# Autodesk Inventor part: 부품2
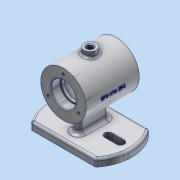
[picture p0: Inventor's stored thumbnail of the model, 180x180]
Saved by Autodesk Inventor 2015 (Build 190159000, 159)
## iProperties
Created: 2017-12
Part Number: 부품2
Material: 알루미늄 6061
Document SubType Name: Modeling
Designer: SCD-A03
Density: 2.7 g/cm^3
Appearance: 알루미늄 - 평지
Mass: 465.937 g
Surface Area: 486.734 cm^2
Volume: 172.569 cm^3
Author: SCD-A03
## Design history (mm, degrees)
node "스케치1"
sketch "스케치2"
  geometry: L1 (-42.426, 35)-(42.426, 35); L2 (42.426, -35)-(-42.426, -35); A1 r 55 centre (0, 0) between (-42.426, 35) and (-42.426, -35); A2 r 55 centre (0, 0) between (42.426, -35) and (42.426, 35); 2 further points
  constraints: 4 end point, 4 point on circle, 2 centre point, 1 coincident, 1 horizontal, 1 midpoint, 1 parallel, 1 vertical alignment
  dimensions: "d2" = 84.85281 distance of L2.start L2.end; "d3" = 55 radius of A1; "d4" = 70 distance between parallel lines of L2 L1; "d5" = 55 radius of A2
extrude "돌출1" new body sketch "스케치2" distance "d6" = 10; taper "d7" = 0 deg
sketch "스케치3"
  geometry: L1 (-40, 0)-(-24, 0); L2 (-40, -5)-(-24, -5); L3 (-24, 5)-(-40, 5); A1 r 55 centre (0, 0) between (-42.426, 35) and (-42.426, -35) reference; A2 r 5 centre (-40, 0) between (-40, 5) and (-40, -5); A3 r 5 centre (-24, 0) between (-24, -5) and (-24, 5); 1 further point
  constraints: 8 end point, 4 point on circle, 4 tangent, 2 centre point, 1 horizontal, 1 horizontal alignment, 1 midpoint, 1 parallel
  dimensions: "d8" = 16 distance of L3.start L3.end; "d9" = 24 horizontal distance of A1.centre L3.start; "d11" = 5 radius of A2
extrude "돌출2" cut sketch "스케치3" distance "d12" = 10; taper "d13" = 0 deg
sketch "스케치8"
  geometry: L1 (0, -15)-(0, 15); L2 (-5, -15)-(-5, 15); L3 (5, 15)-(5, -15); A1 r 55 centre (0, 0) between (-42.426, 35) and (-42.426, -35) reference; A2 r 5 centre (0, -15) between (-5, -15) and (5, -15); A3 r 5 centre (0, 15) between (5, 15) and (-5, 15); 1 further point
  constraints: 8 end point, 4 point on circle, 4 tangent, 2 centre point, 1 coincident, 1 midpoint, 1 parallel, 1 vertical
  dimensions: "d18" = 5 radius of A2; "d19" = 30 distance of L3.start L3.end
extrude "돌출4" join sketch "스케치8" distance "d20" = 52; taper "d21" = 0 deg
sketch "스케치9"
  geometry: L1 (-42.426, 0)-(42.426, 0) reference; C1 r 30 at (0, 62); 1 further point
  constraints: 1 centre point
  dimensions: "d22" = 60 diameter of C1; "d23" = 62 distance from line of L1 C1.centre
extrude "돌출5" join sketch "스케치9" stored distance "d24" = 70; taper "d25" = 0 deg
hole "구멍1" diameter "d28" = 32; stored, may be unused: countersink angle "d32" = 90 deg, drill point angle "d34" = 0 deg; dims "d29" = 6, "d30" = 4, "d31" = 2, "d33" = 12, "d44" = 10, "d45" = 10
hole "구멍2" diameter "d37" = 28; stored, may be unused: countersink angle "d41" = 90 deg, drill point angle "d43" = 0 deg; dims "d35" = 10, "d36" = 10, "d38" = 6, "d39" = 4, "d40" = 2, "d42" = 3
hole "구멍3" diameter "d48" = 50; stored, may be unused: countersink angle "d52" = 90 deg, drill point angle "d54" = 0 deg; dims "d46" = 10, "d47" = 10, "d49" = 6, "d50" = 4, "d51" = 2, "d53" = 20
fillet "모깎기1" dims "d55" = 3
chamfer "모따기1" distance "d56" = 1; stored, may be unused: second distance "d57" = 2, angle "d58" = 45 deg
chamfer "모따기2" distance "d59" = 1; stored, may be unused: second distance "d60" = 2, angle "d61" = 45 deg
node "작업 평면1"
sketch "스케치11"
  geometry: C1 r 8 at (0, 0); 1 further point
  constraints: 1 centre point, 1 coincident
  dimensions: "d63" = 16 diameter of C1
extrude "돌출6" join sketch "스케치11" stored distance "d64" = 70; taper "d65" = 0 deg
hole "구멍4" diameter "d68" = 8; stored, may be unused: countersink angle "d72" = 90 deg, drill point angle "d74" = 0 deg; dims "d66" = 10, "d67" = 10, "d69" = 6, "d70" = 4, "d71" = 2, "d73" = 20
sketch "스케치12"
  geometry: C1 r 30 at (0, 0) reference; 2 further points
  constraints: 1 vertical alignment
  dimensions: "d75" = 23 distance of C1.centre point (0, 23)
hole "구멍5" sketch "스케치12" at (0, 23) diameter "d76" = 3.242; stored, may be unused: countersink angle "d80" = 90 deg, drill point angle "d82" = 118 deg; dims "d77" = 8, "d78" = 4, "d79" = 2, "d81" = 10
fillet "모깎기2" dims "d86" = 0.3
chamfer "모따기3" distance "d88" = 1; stored, may be unused: second distance "d89" = 2, angle "d90" = 45 deg
fillet "모깎기4" dims "d91" = 3
fillet "모깎기5" dims "d92" = 5
fillet "모깎기6" dims "d93" = 3
fillet "모깎기7" dims "d94" = 3
node "작업 평면2"
sketch "스케치13"
  geometry: L1 (35, 7)-(35, 0) reference; L2 (35, 0)-(5, 0) reference; L3 (5, 0)-(5, 10) reference; L4 (5, 10)-(32, 10) reference; L5 (-32, 10)-(-5, 10) reference; L6 (-5, 10)-(-5, 0) reference; L7 (-5, 0)-(-35, 0) reference; L8 (-35, 0)-(-35, 7) reference; L9 (-35, 62)-(35, 62) reference; L10 (35, 7)-(35, 0) reference; L11 (35, 0)-(5, 0) reference; L12 (5, 0)-(5, 10) reference; L13 (5, 10)-(32, 10) reference; L14 (-32, 10)-(-5, 10) reference; L15 (-5, 10)-(-5, 0) reference; L16 (-5, 0)-(-35, 0) reference; L17 (-35, 0)-(-35, 7) reference; L18 (-35, 62)-(35, 62) reference; L19 (-35, 92)-(-35, 32) reference; L20 (-35, 92)-(35, 92) reference; A1 r 3 centre (32, 7) between (35, 7) and (32, 10) reference; A2 r 3 centre (-32, 7) between (-32, 10) and (-35, 7) reference; A3 r 3 centre (32, 7) between (35, 7) and (32, 10) reference; A4 r 3 centre (-32, 7) between (-32, 10) and (-35, 7) reference; 2 further points
  constraints: 1 other
  dimensions: "d97" = 35 distance from line of L19 point (0, 62); "d98" = 30 distance from line of point (0, 62) L20
feature "엠보싱1" sketch "스케치13" dims "d99" = 1, "d100" = 0
node "솔리드1"
mirror "대칭1"
mirror "대칭3"
pattern_circular "원형 패턴1" dims angle "d84" = 360 deg
mirror "대칭4"
node "절단 모서리 투영1"
node "절단 모서리 투영2"
other parameters: "d62" = 99
